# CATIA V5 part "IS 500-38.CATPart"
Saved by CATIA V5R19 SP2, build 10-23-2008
Part number: IS 500-38
Bounding box of the stored display mesh (mm): x -22.494 to 22.494, y -22.494 to 22.494, z 0 to 161
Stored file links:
  C:\Users\Bora\Desktop\3D Katı model\IS serisi\IS 500\IS 500-38.CATPart
  C:\Program Files\Dassault Systemes\B19\intel_a\reffiles\standard\MetricThickPitch.txt
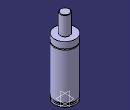
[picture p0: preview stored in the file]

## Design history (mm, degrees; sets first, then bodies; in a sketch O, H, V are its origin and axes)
Body1 (main body)
  Sketch1 on yz-plane, origin (0, 0, 0), H (0, 1, 0), V (0, 0, 1)
    point P3 (10, 160)
    point P5 (10, 160)
    point P7 (22.5, 107.5)
    point P8 (22.5, 105.5)
    point P12 (22.5, 105.5)
    point P13 (22.5, 107.5)
    line L1 (22.5, 0) -> (22.5, 4)
    line L2 (10, 160) -> (10, 121)
    arc A1 centre (9, 160) radius 1 from (10, 160) to (9, 161) ccw
    arc A2 centre (22.5, 106.5) radius 1 from (22.5, 107.5) to (22.5, 105.5) ccw
    line L3 (20, 7.5) -> (20, 4)
    line L4 (22.5, 7.5) -> (22.5, 105.5)
    line L5 (22.5, 107.5) -> (22.5, 121)
    line L6 (9, 161) -> (0, 161)
    point P15 (0, 161)
    line L7 (10, 121) -> (22.5, 121)
    line L8 (20, 7.5) -> (22.5, 7.5)
    line L9 (20, 4) -> (22.5, 4)
    line L10 (0, 0) -> (22.5, 0)
    coincidence: P15 V, P3 P5, P7 P13, P8 P12
    tangency: L6 A1
    horizontal: L7 H, L8 H, L9 H, L10 H
  Shaft1: profile Sketch1, axis Sketch1.V, angle 360
  Sketch2 on face of Shaft1 from Sketch1.L10, origin (0, 0, 0), H (1, 0, 0), V (0, -1, 0)
    point P1 (10, 0)
    distance P1 V = 10
  Hole1: placed by Sketch2, at (10, 0, 0) direction (0, 0, 1), diameter 6.647, depth 13, threaded "M8", thread diameter 8, thread depth 13, pitch 1.25
  Sketch3 on face of Shaft1 from Sketch1.L10, origin (0, 0, 0), H (1, 0, 0), V (0, -1, 0)
    point P1 (-10, 0)
    distance P1 V = 10
  Hole2: placed by Sketch3, at (-10, 0, 0) direction (0, 0, 1), diameter 6.647, depth 13, threaded "M8", thread diameter 8, thread depth 13, pitch 1.25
